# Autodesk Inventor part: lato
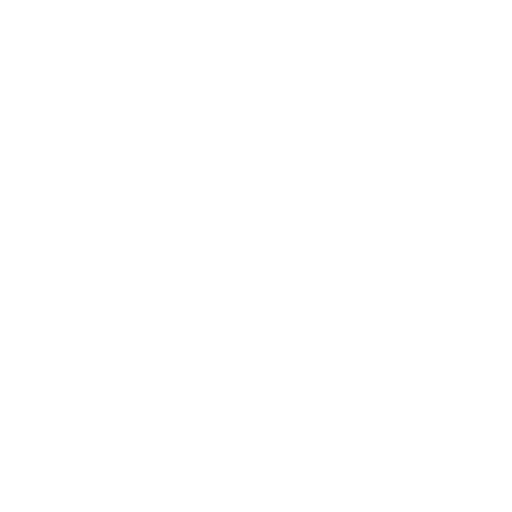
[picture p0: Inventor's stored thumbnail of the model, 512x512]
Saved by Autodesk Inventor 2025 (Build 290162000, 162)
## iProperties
Created: 2025-05
Part Number: lato
Material: Plastica PET
Document SubType Name: Modeling
Designer: R5800u
Density: 1.541 g/cm^3
Appearance: Acciaio - Lucido
Author: R5800u
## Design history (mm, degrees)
sketch "Schizzo1"
  geometry: L1 (300, -48)-(300, -53) reference
extrude "Estrusione1" new body sketch "Schizzo1" distance "d3" = 120; taper "d4" = 0 deg
sketch "Schizzo2"
  geometry: L1 (0, 53)-(0, 0) reference; L2 (0, 53)-(-120, 53) reference; L3 (-120, 0)-(-120, 53) reference; L4 (0, 0)-(-120, 0) reference; L5 (-112.5, 45.5)-(-7.5, 45.5); L6 (-7.5, 45.5)-(-7.5, 7.5); L7 (-7.5, 7.5)-(-112.5, 7.5); L8 (-112.5, 7.5)-(-112.5, 45.5); L9 (-102.5, 45.5)-(-102.5, 43.336); L10 (-102.5, 43.336)-(-102.5, 7.5); 1 further point
  constraints: 12 end point, 3 point on line, 1 perpendicular, 3 other
  dimensions: "d5" = 7.5 distance between parallel lines of L2 L5; "d39" = 10 distance between parallel lines of L8 L10
extrude "Estrusione2" cut sketch "Schizzo2" stored distance "d6" = 10; taper "d7" = 0 deg
sketch "Schizzo3"
  geometry: L1 (81.5, -69.5)-(81.5, -61.5) reference; L2 (93.5, -69.5)-(81.5, -69.5) reference; L3 (93.5, -61.5)-(93.5, -69.5) reference; L4 (81.5, -61.5)-(93.5, -61.5) reference; L5 (93.5, 61.5)-(81.5, 61.5) reference; L6 (81.5, 61.5)-(81.5, 69.5) reference; L7 (81.5, 69.5)-(93.5, 69.5) reference; 1 further point
  constraints: 14 end point, 4 horizontal, 3 vertical, 8 other
extrude "Estrusione3" cut sketch "Schizzo3" distance "d8" = 10; taper "d9" = 0 deg
sketch "Schizzo4"
  geometry: L1 (0, -120)-(140, -120) reference; L2 (100, -120)-(100, 0); L3 (0, 0)-(140, 0) reference; L4 (100, -60)-(110, -63.75); L5 (100, -10)-(10, -10); L6 (0, 0)-(0, -120) reference; 7 further points; 1 other entity
  constraints: 6 end point, 3 point on line, 1 coincident, 1 horizontal, 1 midpoint, 1 symmetric about line, 1 vertical, 2 other
  dimensions: "d11" = 10 distance from line of L4 point (100, -70.68); "d19" = 10 distance from line of L6 L5.end; "d34" = 10 dimension on L2; "d35" = 30 distance from line of L1 point (100, -90)
hole "Foro1" sketch "Schizzo4" at (100, -90), (100, -10), (10, -10), (10, -110) diameter "d12" = 4.5; stored, may be unused: countersink angle "d16" = 90 deg, drill point angle "d18" = 118 deg; dims "d13" = 6, "d14" = 9.4, "d15" = 2, "d17" = 20
node "Piano di lavoro1"
sketch "Schizzo6"
  geometry: C1 r 2.25 at (95, 90) reference; C2 r 2.25 at (95, 10) reference; 1 further point
hole "Foro2" sketch "Schizzo6" at (95, 10), (95, 90) diameter "d21" = 5.5; stored, may be unused: countersink angle "d25" = 90 deg, drill point angle "d27" = 118 deg; dims "d22" = 6, "d23" = 9, "d24" = 8, "d26" = 20
node "Piano di lavoro2"
sketch "Schizzo8"
  geometry: L1 (-120, 87.744)-(0, 87.744) reference; 1 further point
extrude "Estrusione5" cut sketch "Schizzo8" extent not by distance; stored distance "d37" = 0; taper "d38" = 0 deg
node "Solido1"
node "Riferimento2"
node "Linea chiusa proiettata1"
other parameters: "d20" = 11
